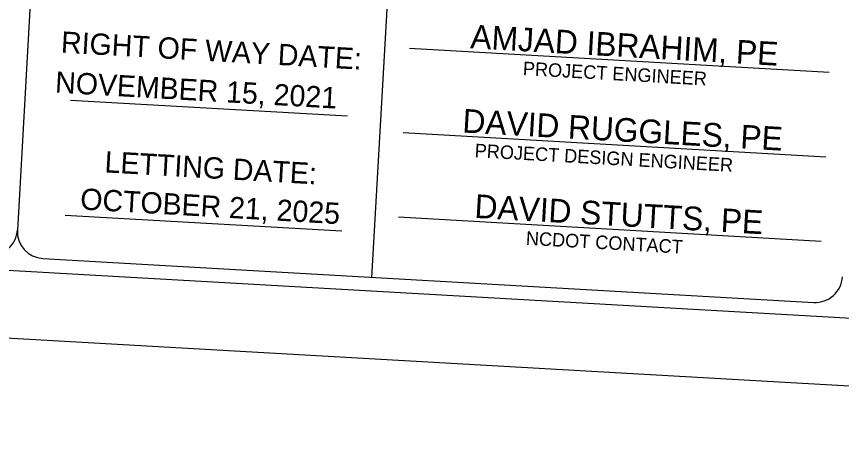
# Model space of a CAD drawing. Extents: x 2601627 to 2606907, y 616646 to 620530.
# Drawn here: x 2604538 to 2605452, y 616945 to 617426 of the extents above; entities that cross this region are included whole.
import ezdxf

# ---------------------------------------------------------------- set-up
doc = ezdxf.new("R2010")
doc.units = 0
for name, color, linetype in [('Sheet Data Field CELL', 7, 'Continuous'), ('Sheet Title CELL', 7, 'Continuous'), ('Stewart Plot Border Xerox6279 and LJ5000', 7, 'Continuous')]:
    doc.layers.add(name, color=color, linetype=linetype)

msp = doc.modelspace()

# ---------------------------------------------------------------- linework, layer by layer
at = {"layer": 'Sheet Title CELL'}
for p, q in [((2604566.58, 617668.41), (2604539.29, 617189.18)), ((2604950.78, 617473.73), (2604931.59, 617136.79)), ((2604973.56, 617390.78), (2605438.25, 617364.22)), ((2604904.95, 617315.54), (2604598.32, 617333)), ((2604966.58, 617297.27), (2605434.56, 617270.56)), ((2604747.69, 617256.24), (2604747.69, 617256.24)), ((2604898.76, 617187.93), (2604592.13, 617205.4)), ((2604961.25, 617203.7), (2605429.23, 617176.99))]:
    msp.add_line(p, q, dxfattribs=at)
for points in [[(2602185.54, 617278.13), (2606618.35, 617025.66)], [(2604567.53, 617157.52), (2605421.15, 617108.87)]]:
    msp.add_lwpolyline(points, dxfattribs=at)
for centre, start, end in [((2604509.36, 617191.02), 266.74026, 356.74026), ((2604569.26, 617187.61), 176.74026, 266.74026), ((2605422.88, 617138.99), 266.74026, 356.74026)]:
    msp.add_arc(centre, 30, start, end, dxfattribs=at)
at = {"layer": 'Stewart Plot Border Xerox6279 and LJ5000'}
msp.add_lwpolyline([(2601627.15, 617234.85), (2606718.89, 616944.81), (2606906.57, 620239.47), (2601814.82, 620529.51)], close=True, dxfattribs=at)

# ---------------------------------------------------------------- texts
at = {"layer": 'Sheet Data Field CELL'}
for s, height, rotation, p in [('AMJAD IBRAHIM, PE', 26.2503, 356.73351, (2605040.45, 617390.83)), ('NOVEMBER 15, 2021', 23.6253, 356.74026, (2604580.65, 617341.63)), ('DAVID RUGGLES, PE', 26.2503, 356.73351, (2605031.63, 617297.43)), ('OCTOBER 21, 2025', 23.6253, 356.74026, (2604608.45, 617212.09)), ('DAVID STUTTS, PE', 26.2503, 356.73351, (2605045.04, 617202.78))]:
    msp.add_text(s, height=height, rotation=rotation, dxfattribs=at).set_placement(p)
at = {"layer": 'Sheet Title CELL'}
for s, height, rotation, p in [('RIGHT OF WAY DATE: ', 23.6245, 356.74026, (2604587.14, 617385.97)), ('PROJECT ENGINEER', 14.9985, 356.73351, (2605098.75, 617361.09)), ('PROJECT DESIGN ENGINEER', 14.9985, 356.73351, (2605045.4, 617270.05)), ('LETTING DATE:', 23.6245, 356.74026, (2604635.42, 617253.2)), ('NCDOT CONTACT', 14.9985, 356.73351, (2605102.11, 617172.93))]:
    msp.add_text(s, height=height, rotation=rotation, dxfattribs=at).set_placement(p)

doc.saveas('drawing.dxf')
